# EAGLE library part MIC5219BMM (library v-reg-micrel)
VOLTAGE REGULATOR
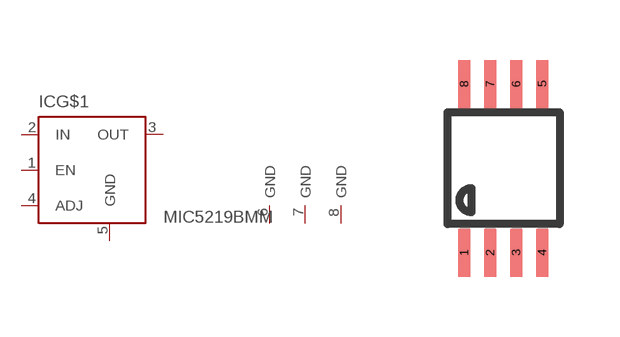
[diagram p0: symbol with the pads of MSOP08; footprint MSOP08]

Designator prefix IC; gates G1=GND G2=GND G3=GND G$1=MIC5219A

## MIC5219BMM  [MSOP08]
1  G$1:EN  in
2  G$1:IN  in
3  G$1:OUT  out
4  G$1:ADJ  pas
5  G$1:GND  pwr
6  G1:GND  pwr
7  G2:GND  pwr
8  G3:GND  pwr

## Footprint MSOP08 (pad centres in mm)
Mini Small Outline Package
smd 0.3 x 1.2: 1 -0.976,-2.113; 2 -0.326,-2.113; 3 0.324,-2.113; 4 0.974,-2.113; 5 0.974,2.112; 6 0.324,2.112; 7 -0.326,2.112; 8 -0.976,2.112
